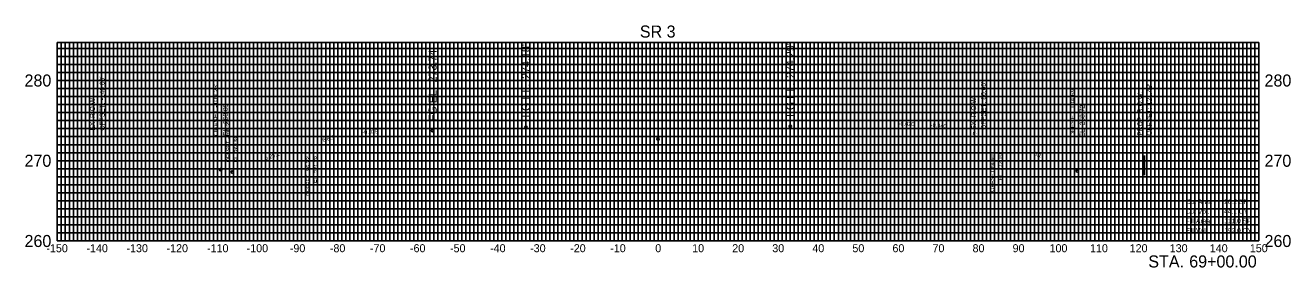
# Model space of a CAD drawing. Extents: x -158 to 158, y 253 to 314.
import ezdxf

# ---------------------------------------------------------------- set-up
doc = ezdxf.new("R2010")
doc.units = 0
for name, color, linetype in [('Default', 7, 'Continuous'), ('DES - ROW - Linework', 7, 'Continuous'), ('DES - SHEET - Light Grid', 7, 'Continuous'), ('DES - SHEET - Linework', 7, 'Continuous'), ('DES - XS - Proposed - Finished Grade Slopes Text', 7, 'Continuous'), ('DES - XS - Proposed - Subgrade Tie Text', 7, 'Continuous'), ('DES - XS - Proposed - Text', 7, 'Continuous'), ('SUR - PROPERTY - ROW Lines', 7, 'Continuous')]:
    doc.layers.add(name, color=color, linetype=linetype)

msp = doc.modelspace()

# ---------------------------------------------------------------- linework, layer by layer
at = {"layer": 'DES - ROW - Linework'}
msp.add_line((121.48, 276.42), (121.48, 281.34), dxfattribs=at)
at = {"layer": 'DES - SHEET - Light Grid'}
for p, q in [((-150, 308), (150, 308)), ((-149, 260), (-149, 309.5)), ((-148, 260), (-148, 309.5)), ((-147, 260), (-147, 309.5)), ((-146, 260), (-146, 309.5)), ((-145, 260), (-145, 309.5)), ((-144, 260), (-144, 309.5)), ((-143, 260), (-143, 309.5)), ((-142, 260), (-142, 309.5)), ((-141, 260), (-141, 309.5)), ((-139, 260), (-139, 309.5)), ((-138, 260), (-138, 309.5)), ((-137, 260), (-137, 309.5)), ((-136, 260), (-136, 309.5)), ((-135, 260), (-135, 309.5)), ((-134, 260), (-134, 309.5)), ((-133, 260), (-133, 309.5)), ((-132, 260), (-132, 309.5)), ((-131, 260), (-131, 309.5)), ((-129, 260), (-129, 309.5)), ((-128, 260), (-128, 309.5)), ((-127, 260), (-127, 309.5)), ((-126, 260), (-126, 309.5)), ((-125, 260), (-125, 309.5)), ((-124, 260), (-124, 309.5)), ((-123, 260), (-123, 309.5)), ((-122, 260), (-122, 309.5)), ((-121, 260), (-121, 309.5)), ((-119, 260), (-119, 309.5)), ((-118, 260), (-118, 309.5)), ((-117, 260), (-117, 309.5)), ((-116, 260), (-116, 309.5)), ((-115, 260), (-115, 309.5)), ((-114, 260), (-114, 309.5)), ((-113, 260), (-113, 309.5)), ((-112, 260), (-112, 309.5)), ((-111, 260), (-111, 309.5)), ((-109, 260), (-109, 309.5)), ((-108, 260), (-108, 309.5)), ((-107, 260), (-107, 309.5)), ((-106, 260), (-106, 309.5)), ((-105, 260), (-105, 309.5)), ((-104, 260), (-104, 309.5)), ((-103, 260), (-103, 309.5)), ((-102, 260), (-102, 309.5)), ((-101, 260), (-101, 309.5)), ((-99, 260), (-99, 309.5)), ((-98, 260), (-98, 309.5)), ((-97, 260), (-97, 309.5)), ((-96, 260), (-96, 309.5)), ((-95, 260), (-95, 309.5)), ((-94, 260), (-94, 309.5)), ((-93, 260), (-93, 309.5)), ((-92, 260), (-92, 309.5)), ((-91, 260), (-91, 309.5)), ((-89, 260), (-89, 309.5)), ((-88, 260), (-88, 309.5)), ((-87, 260), (-87, 309.5)), ((-86, 260), (-86, 309.5)), ((-85, 260), (-85, 309.5)), ((-84, 260), (-84, 309.5)), ((-83, 260), (-83, 309.5)), ((-82, 260), (-82, 309.5)), ((-81, 260), (-81, 309.5)), ((-79, 260), (-79, 309.5)), ((-78, 260), (-78, 309.5)), ((-77, 260), (-77, 309.5)), ((-76, 260), (-76, 309.5)), ((-75, 260), (-75, 309.5)), ((-74, 260), (-74, 309.5)), ((-73, 260), (-73, 309.5)), ((-72, 260), (-72, 309.5)), ((-71, 260), (-71, 309.5)), ((-69, 260), (-69, 309.5)), ((-68, 260), (-68, 309.5)), ((-67, 260), (-67, 309.5)), ((-66, 260), (-66, 309.5)), ((-65, 260), (-65, 309.5)), ((-64, 260), (-64, 309.5)), ((-63, 260), (-63, 309.5)), ((-62, 260), (-62, 309.5)), ((-61, 260), (-61, 309.5)), ((-59, 260), (-59, 309.5)), ((-58, 260), (-58, 309.5)), ((-57, 260), (-57, 309.5)), ((-56, 260), (-56, 309.5)), ((-55, 260), (-55, 309.5)), ((-54, 260), (-54, 309.5)), ((-53, 260), (-53, 309.5)), ((-52, 260), (-52, 309.5)), ((-51, 260), (-51, 309.5)), ((-49, 260), (-49, 309.5)), ((-48, 260), (-48, 309.5)), ((-47, 260), (-47, 309.5)), ((-46, 260), (-46, 309.5)), ((-45, 260), (-45, 309.5)), ((-44, 260), (-44, 309.5)), ((-43, 260), (-43, 309.5)), ((-42, 260), (-42, 309.5)), ((-41, 260), (-41, 309.5)), ((-39, 260), (-39, 309.5)), ((-38, 260), (-38, 309.5)), ((-37, 260), (-37, 309.5)), ((-36, 260), (-36, 309.5)), ((-35, 260), (-35, 309.5)), ((-34, 260), (-34, 309.5)), ((-33, 260), (-33, 309.5)), ((-32, 260), (-32, 309.5)), ((-31, 260), (-31, 309.5)), ((-29, 260), (-29, 309.5)), ((-28, 260), (-28, 309.5)), ((-27, 260), (-27, 309.5)), ((-26, 260), (-26, 309.5)), ((-25, 260), (-25, 309.5)), ((-24, 260), (-24, 309.5)), ((-23, 260), (-23, 309.5)), ((-22, 260), (-22, 309.5)), ((-21, 260), (-21, 309.5)), ((-19, 260), (-19, 309.5)), ((-18, 260), (-18, 309.5)), ((-17, 260), (-17, 309.5)), ((-16, 260), (-16, 309.5)), ((-15, 260), (-15, 309.5)), ((-14, 260), (-14, 309.5)), ((-13, 260), (-13, 309.5)), ((-12, 260), (-12, 309.5)), ((-11, 260), (-11, 309.5)), ((-9, 260), (-9, 309.5)), ((-8, 260), (-8, 309.5)), ((-7, 260), (-7, 309.5)), ((-6, 260), (-6, 309.5)), ((-5, 260), (-5, 309.5)), ((-4, 260), (-4, 309.5)), ((-3, 260), (-3, 309.5)), ((-2, 260), (-2, 309.5)), ((-1, 260), (-1, 309.5)), ((1, 260), (1, 309.5)), ((2, 260), (2, 309.5)), ((3, 260), (3, 309.5)), ((4, 260), (4, 309.5)), ((5, 260), (5, 309.5)), ((6, 260), (6, 309.5)), ((7, 260), (7, 309.5)), ((8, 260), (8, 309.5)), ((9, 260), (9, 309.5)), ((11, 260), (11, 309.5)), ((12, 260), (12, 309.5)), ((13, 260), (13, 309.5)), ((14, 260), (14, 309.5)), ((15, 260), (15, 309.5)), ((16, 260), (16, 309.5)), ((17, 260), (17, 309.5)), ((18, 260), (18, 309.5)), ((19, 260), (19, 309.5)), ((21, 260), (21, 309.5)), ((22, 260), (22, 309.5)), ((23, 260), (23, 309.5)), ((24, 260), (24, 309.5)), ((25, 260), (25, 309.5)), ((26, 260), (26, 309.5)), ((27, 260), (27, 309.5)), ((28, 260), (28, 309.5)), ((29, 260), (29, 309.5)), ((31, 260), (31, 309.5)), ((32, 260), (32, 309.5)), ((33, 260), (33, 309.5)), ((34, 260), (34, 309.5)), ((35, 260), (35, 309.5)), ((36, 260), (36, 309.5)), ((37, 260), (37, 309.5)), ((38, 260), (38, 309.5)), ((39, 260), (39, 309.5)), ((41, 260), (41, 309.5)), ((42, 260), (42, 309.5)), ((43, 260), (43, 309.5)), ((44, 260), (44, 309.5)), ((45, 260), (45, 309.5)), ((46, 260), (46, 309.5)), ((47, 260), (47, 309.5)), ((48, 260), (48, 309.5)), ((49, 260), (49, 309.5)), ((51, 260), (51, 309.5)), ((52, 260), (52, 309.5)), ((53, 260), (53, 309.5)), ((54, 260), (54, 309.5)), ((55, 260), (55, 309.5)), ((56, 260), (56, 309.5)), ((57, 260), (57, 309.5)), ((58, 260), (58, 309.5)), ((59, 260), (59, 309.5)), ((61, 260), (61, 309.5)), ((62, 260), (62, 309.5)), ((63, 260), (63, 309.5)), ((64, 260), (64, 309.5)), ((65, 260), (65, 309.5)), ((66, 260), (66, 309.5)), ((67, 260), (67, 309.5)), ((68, 260), (68, 309.5)), ((69, 260), (69, 309.5)), ((71, 260), (71, 309.5)), ((72, 260), (72, 309.5)), ((73, 260), (73, 309.5)), ((74, 260), (74, 309.5)), ((75, 260), (75, 309.5)), ((76, 260), (76, 309.5)), ((77, 260), (77, 309.5)), ((78, 260), (78, 309.5)), ((79, 260), (79, 309.5)), ((81, 260), (81, 309.5)), ((82, 260), (82, 309.5)), ((83, 260), (83, 309.5)), ((84, 260), (84, 309.5)), ((85, 260), (85, 309.5)), ((86, 260), (86, 309.5)), ((87, 260), (87, 309.5)), ((88, 260), (88, 309.5)), ((89, 260), (89, 309.5)), ((91, 260), (91, 309.5)), ((92, 260), (92, 309.5)), ((93, 260), (93, 309.5)), ((94, 260), (94, 309.5)), ((95, 260), (95, 309.5)), ((96, 260), (96, 309.5)), ((97, 260), (97, 309.5)), ((98, 260), (98, 309.5)), ((99, 260), (99, 309.5)), ((101, 260), (101, 309.5)), ((102, 260), (102, 309.5)), ((103, 260), (103, 309.5)), ((104, 260), (104, 309.5)), ((105, 260), (105, 309.5)), ((106, 260), (106, 309.5)), ((107, 260), (107, 309.5)), ((108, 260), (108, 309.5)), ((109, 260), (109, 309.5)), ((111, 260), (111, 309.5)), ((112, 260), (112, 309.5)), ((113, 260), (113, 309.5)), ((114, 260), (114, 309.5)), ((115, 260), (115, 309.5)), ((116, 260), (116, 309.5)), ((117, 260), (117, 309.5)), ((118, 260), (118, 309.5)), ((119, 260), (119, 309.5)), ((121, 260), (121, 309.5)), ((122, 260), (122, 309.5)), ((123, 260), (123, 309.5)), ((124, 260), (124, 309.5)), ((125, 260), (125, 309.5)), ((126, 260), (126, 309.5)), ((127, 260), (127, 309.5)), ((128, 260), (128, 309.5)), ((129, 260), (129, 309.5)), ((131, 260), (131, 309.5)), ((132, 260), (132, 309.5)), ((133, 260), (133, 309.5)), ((134, 260), (134, 309.5)), ((135, 260), (135, 309.5)), ((136, 260), (136, 309.5)), ((137, 260), (137, 309.5)), ((138, 260), (138, 309.5)), ((139, 260), (139, 309.5)), ((141, 260), (141, 309.5)), ((142, 260), (142, 309.5)), ((143, 260), (143, 309.5)), ((144, 260), (144, 309.5)), ((145, 260), (145, 309.5)), ((146, 260), (146, 309.5)), ((147, 260), (147, 309.5)), ((148, 260), (148, 309.5)), ((149, 260), (149, 309.5)), ((-150, 306), (150, 306)), ((-150, 304), (150, 304)), ((-150, 302), (150, 302)), ((-150, 298), (150, 298)), ((-150, 296), (150, 296)), ((-150, 294), (150, 294)), ((-150, 292), (150, 292)), ((-150, 290), (150, 290)), ((-150, 288), (150, 288)), ((-150, 286), (150, 286)), ((-150, 284), (150, 284)), ((-150, 282), (150, 282)), ((-150, 278), (150, 278)), ((-150, 276), (150, 276)), ((-150, 274), (150, 274)), ((-150, 272), (150, 272)), ((-150, 270), (150, 270)), ((-150, 268), (150, 268)), ((-150, 266), (150, 266)), ((-150, 264), (150, 264)), ((-150, 262), (150, 262))]:
    msp.add_line(p, q, dxfattribs=at)
at = {"layer": 'DES - SHEET - Linework'}
for p, q in [((-150, 309.5), (150, 309.5)), ((-150, 260), (-150, 309.5)), ((-140, 260), (-140, 309.5)), ((-130, 260), (-130, 309.5)), ((-120, 260), (-120, 309.5)), ((-110, 260), (-110, 309.5)), ((-100, 260), (-100, 309.5)), ((-90, 260), (-90, 309.5)), ((-80, 260), (-80, 309.5)), ((-70, 260), (-70, 309.5)), ((-60, 260), (-60, 309.5)), ((-50, 260), (-50, 309.5)), ((-40, 260), (-40, 309.5)), ((-30, 260), (-30, 309.5)), ((-20, 260), (-20, 309.5)), ((-10, 260), (-10, 309.5)), ((0, 260), (0, 309.5)), ((10, 260), (10, 309.5)), ((20, 260), (20, 309.5)), ((30, 260), (30, 309.5)), ((40, 260), (40, 309.5)), ((50, 260), (50, 309.5)), ((60, 260), (60, 309.5)), ((70, 260), (70, 309.5)), ((80, 260), (80, 309.5)), ((90, 260), (90, 309.5)), ((100, 260), (100, 309.5)), ((110, 260), (110, 309.5)), ((120, 260), (120, 309.5)), ((130, 260), (130, 309.5)), ((140, 260), (140, 309.5)), ((150, 260), (150, 309.5)), ((-150, 300), (150, 300)), ((-150, 280), (150, 280)), ((-150, 260), (150, 260))]:
    msp.add_line(p, q, dxfattribs=at)
at = {"layer": 'DES - XS - Proposed - Finished Grade Slopes Text'}
for centre in [(-109.23, 277.79), (104.69, 277.44)]:
    msp.add_circle(centre, 0.3, dxfattribs=at)
at = {"layer": 'DES - XS - Proposed - Text'}
for centre in [(-56.31, 287.48), (-33, 288.36), (33, 288.57), (0, 285.43), (-106.32, 277.18)]:
    msp.add_circle(centre, 0.3, dxfattribs=at)
at = {"layer": 'SUR - PROPERTY - ROW Lines'}
for p, q in [((-140, 277.68), (-140, 282.6)), ((80, 277.86), (80, 282.78))]:
    msp.add_line(p, q, dxfattribs=at)

# ---------------------------------------------------------------- texts
at = {"layer": 'Default'}
for s, p in [('Cut Area', (131.74, 269.2)), ('26.2 SF', (141.34, 269.2)), ('Cut Vol.        44.1 CY', (131.74, 266.8)), ('Fill Area', (131.74, 264.4)), ('111.0 SF', (141.34, 264.4)), ('Fill Vol.', (131.74, 262)), ('192.0 CY', (141.34, 262))]:
    msp.add_text(s, height=1.2, dxfattribs=at).set_placement(p)
at = {"layer": 'DES - ROW - Linework'}
for s, p in [("121.48'", (123.28, 293.81)), ('PROP. R.O.W.', (120.88, 286.26)), ('OFFSET: ', (123.28, 286.26))]:
    msp.add_text(s, height=1.2, rotation=90, dxfattribs=at).set_placement(p)
at = {"layer": 'DES - XS - Proposed - Finished Grade Slopes Text'}
for s, height, rotation, p in [("-109.23'", 1.2, 90, (-109.83, 293.24)), ("104.69'", 1.2, 90, (104.09, 292.89)), ('268.89', 1.2, 90, (-107.43, 289.17)), ('OFFSET ', 1.2, 90, (-109.83, 286.19)), ('OFFSET ', 1.2, 90, (104.09, 285.84)), ('268.72', 1.2, 90, (106.49, 288.83)), ('EL. ', 1.2, 90, (-107.43, 286.19)), ('-0.039', 1, 4.4117, (-73.79, 286.57)), ('-0.020', 1, 357.7094, (60.06, 288.77)), ('-0.040', 1, 355.4261, (68.06, 288.45)), ('EL. ', 1.2, 90, (106.49, 285.84)), ('6.8:1', 1, 16.3986, (-83.66, 284.64)), ('6:1', 1, 341.5616, (78.4, 286.51)), ('6.28:1', 1, 17.6748, (-98.05, 280.12)), ('6:1', 1, 341.5616, (93.75, 281.39))]:
    msp.add_text(s, height=height, rotation=rotation, dxfattribs=at).set_placement(p)
at = {"layer": 'DES - XS - Proposed - Subgrade Tie Text'}
for s, p in [("84.40'", (83.9, 278.11)), ('272.10', (85.9, 277.6)), ("-86.33'", (-86.83, 276.99)), ('271.78', (-84.83, 276.94)), ('OFFSET ', (-86.83, 271.12)), ('EL. ', (-84.83, 274.46)), ('OFFSET ', (83.9, 272.24)), ('EL. ', (85.9, 275.12))]:
    msp.add_text(s, height=1, rotation=90, dxfattribs=at).set_placement(p)
at = {"layer": 'DES - XS - Proposed - Text'}
for s, height, p in [('SR 3', 3, (-4.56, 310.7)), ('280', 3, (-158.19, 298.5)), ('280', 3, (151.41, 298.5)), ('270', 3, (-158.19, 278.5)), ('270', 3, (151.41, 278.5)), ('260', 3, (-158.19, 258.5)), ('-150', 2, (-152.73, 257.2)), ('-140', 2, (-142.73, 257.2)), ('-130', 2, (-132.73, 257.2)), ('-120', 2, (-122.73, 257.2)), ('-110', 2, (-112.62, 257.2)), ('-100', 2, (-102.73, 257.2)), ('-90', 2, (-91.95, 257.2)), ('-80', 2, (-81.95, 257.2)), ('-70', 2, (-71.95, 257.2)), ('-60', 2, (-61.95, 257.2)), ('-50', 2, (-51.95, 257.2)), ('-40', 2, (-41.95, 257.2)), ('-30', 2, (-31.95, 257.2)), ('-20', 2, (-21.95, 257.2)), ('-10', 2, (-11.95, 257.2)), ('0', 2, (-0.71, 257.2)), ('10', 2, (8.51, 257.2)), ('20', 2, (18.51, 257.2)), ('30', 2, (28.51, 257.2)), ('40', 2, (38.51, 257.2)), ('50', 2, (48.51, 257.2)), ('60', 2, (58.51, 257.2)), ('70', 2, (68.51, 257.2)), ('80', 2, (78.51, 257.2)), ('90', 2, (88.51, 257.2)), ('100', 2, (97.74, 257.2)), ('110', 2, (107.84, 257.2)), ('120', 2, (117.74, 257.2)), ('130', 2, (127.74, 257.2)), ('140', 2, (137.74, 257.2)), ('150', 2, (147.74, 257.2)), ('260', 3, (151.41, 258.5)), (' STA. ', 3, (121.28, 253.4)), ('69+00.00', 3, (132.61, 253.4))]:
    msp.add_text(s, height=height, dxfattribs=at).set_placement(p)
for s, height, p in [("273.74'", 2, (-55.31, 299.51)), ("274.18'", 2, (-32, 300.39)), ("274.29'", 2, (34, 300.6)), ('FG EL. ', 2, (-55.31, 289.88)), ('FG EL. ', 2, (-32, 290.76)), ('FG EL. ', 2, (34, 290.97)), ("-106.32'", 1, (-106.82, 285.46)), ('OFFSET ', 1, (-106.82, 279.58)), ('268.59', 1, (-104.82, 282.07)), ('EL. ', 1, (-104.82, 279.58))]:
    msp.add_text(s, height=height, rotation=90, dxfattribs=at).set_placement(p)
at = {"layer": 'SUR - PROPERTY - ROW Lines'}
for s, p in [("-140.00'", (-138.2, 295.06)), ("80.00'", (81.8, 295.24)), ('EX. R.O.W. ', (-140.6, 287.52)), ('OFFSET: ', (-138.2, 287.52)), ('EX. R.O.W. ', (79.4, 287.7)), ('OFFSET: ', (81.8, 287.7))]:
    msp.add_text(s, height=1.2, rotation=90, dxfattribs=at).set_placement(p)

doc.saveas('drawing.dxf')
